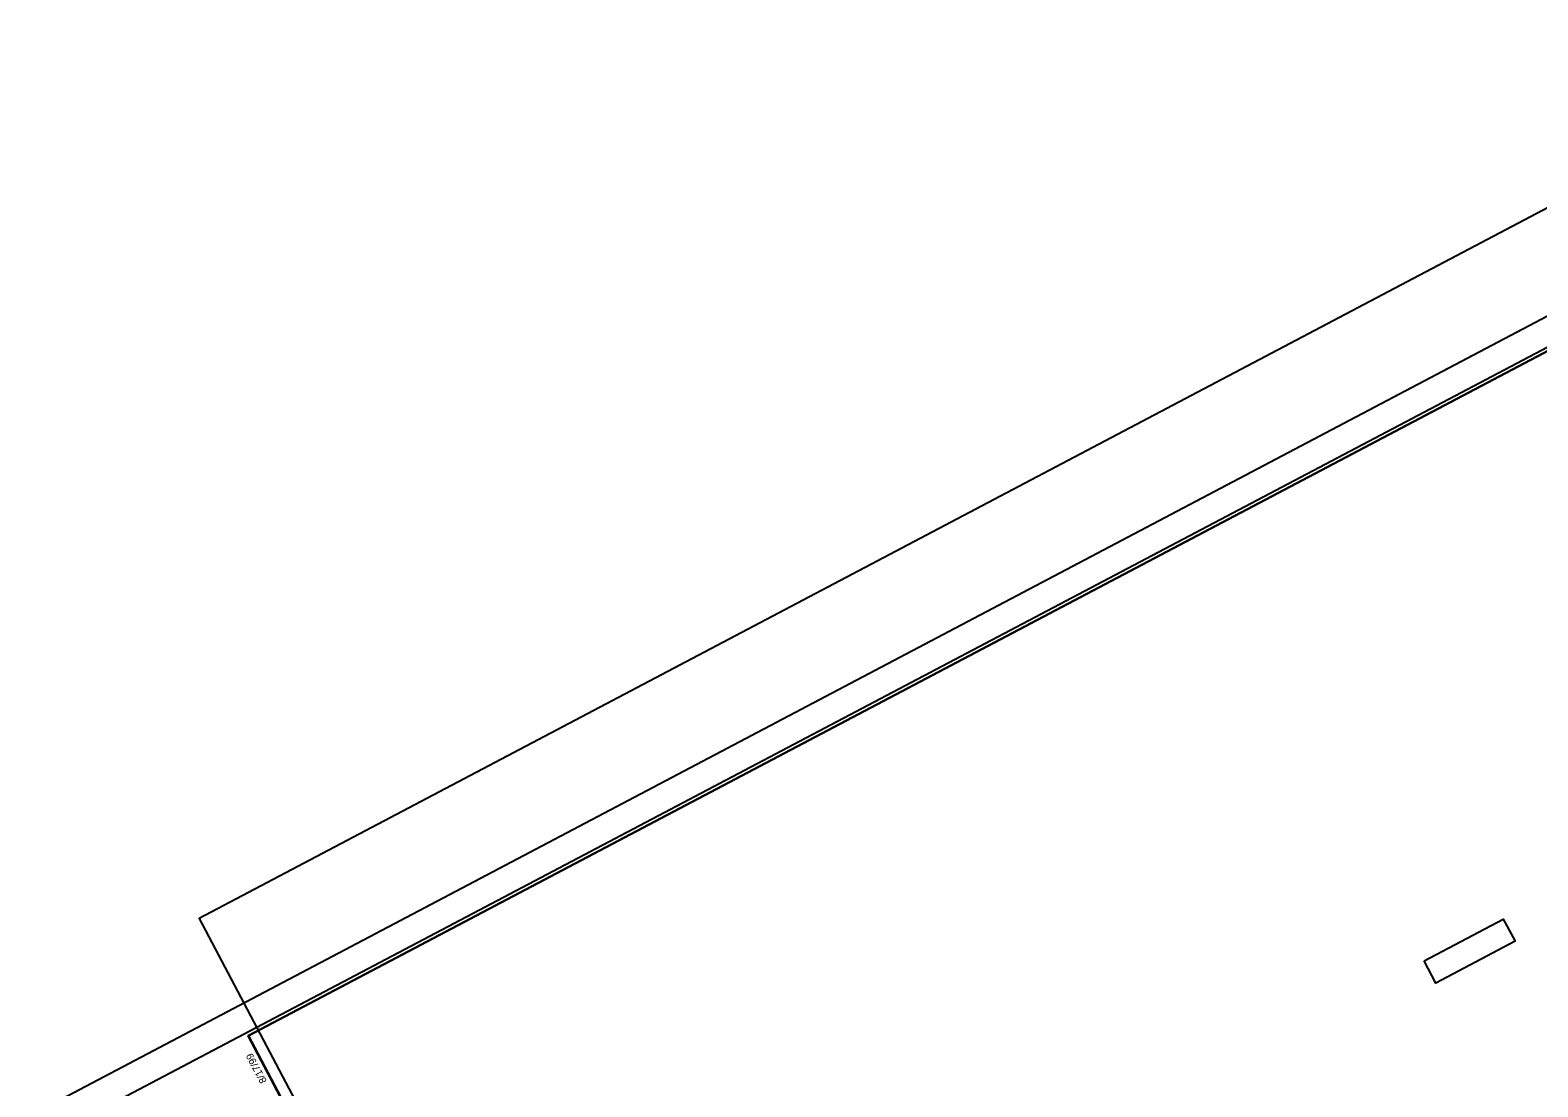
# Model space of a CAD drawing. Extents: x 1380651 to 1383136, y 594581 to 596344.
# Drawn here: x 1380651 to 1381741, y 595571 to 596335 of the extents above; entities that cross this region are included whole.
import ezdxf

# ---------------------------------------------------------------- set-up
doc = ezdxf.new("R2010")
doc.units = 0
for name, color, linetype in [('Prop Shade Light', 7, 'Continuous'), ('Sheet Clip Boundary CELL', 7, 'Continuous'), ('Sheet Cutting Line CELL', 7, 'Continuous'), ('Sheet Layout Plan Border', 7, 'Continuous'), ('Sheet Plan CELL', 7, 'Continuous'), ('Sheet Plot Border Inside CELL', 7, 'Continuous'), ('Sheet Plot Border Outside CELL', 7, 'Continuous')]:
    doc.layers.add(name, color=color, linetype=linetype)

msp = doc.modelspace()

# ---------------------------------------------------------------- linework, layer by layer
at = {"layer": 'Prop Shade Light'}
msp.add_lwpolyline([(1381658.6, 595662.1), (1381715.8, 595692.3), (1381724.3, 595676.3), (1381667, 595646.1)], close=True, dxfattribs=at)
at = {"layer": 'Sheet Clip Boundary CELL'}
msp.add_lwpolyline([(1381254.2, 594780), (1382566.3, 595471.7), (1382154.4, 596253), (1381978.5, 596160.3), (1381909.2, 596291.8), (1380773, 595692.8)], close=True, dxfattribs=at)
at = {"layer": 'Sheet Cutting Line CELL'}
msp.add_line((1382140, 596335.2), (1380650.8, 595550.1), dxfattribs=at)
at = {"layer": 'Sheet Layout Plan Border'}
msp.add_lwpolyline([(1381298.2, 594679), (1382625.1, 595378.5), (1382205.4, 596174.6), (1382028.5, 596081.3), (1381958.5, 596214.1), (1380808.5, 595607.8)], close=True, dxfattribs=at)
at = {"layer": 'Sheet Plan CELL'}
msp.add_line((1380808.6, 595607.8), (1380808.6, 595607.8), dxfattribs=at)
for points in [[(1382135.5, 596307.4), (1380808.6, 595607.8), (1381298.2, 594679), (1382625.1, 595378.5)], [(1381298.2, 594679), (1380808.5, 595607.8), (1381958.5, 596214.1), (1382028.5, 596081.3), (1382205.5, 596174.6), (1382625.1, 595378.5)]]:
    msp.add_lwpolyline(points, close=True, dxfattribs=at)
at = {"layer": 'Sheet Plot Border Inside CELL'}
msp.add_lwpolyline([(1381163.6, 594605.2), (1382637.4, 595382.2), (1382145.4, 596315.4), (1380671.6, 595538.5)], close=True, dxfattribs=at)
at = {"layer": 'Sheet Plot Border Outside CELL'}
msp.add_lwpolyline([(1381161.5, 594581.5), (1382650.7, 595366.6), (1382140, 596335.2), (1380650.8, 595550.1)], close=True, dxfattribs=at)

# ---------------------------------------------------------------- texts
at = {"layer": 'Sheet Plan CELL'}
msp.add_text('8/17/99', height=5.25, rotation=117.7977, dxfattribs=at).set_placement((1380822.1, 595575.2))

doc.saveas('drawing.dxf')
